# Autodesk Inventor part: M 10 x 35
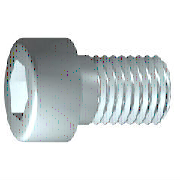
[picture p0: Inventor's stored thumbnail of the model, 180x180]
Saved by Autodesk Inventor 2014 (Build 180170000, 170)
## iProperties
Created: 2009-02
Part Number: M 10 x 35
Material: 강, 연강
Description: 6각머리 태핑 나사
Document SubType Name: Modeling
Standard: KS B 1003
Designer: KYOUNG IL JANG
Standards Organization: KS
Language: ko-KR
Size Designation: M 10 x 35
Categories: <MemberInstance><Categories><Category DisplayName="조임쇠" InternalName="e4da775c-781d-43d5-af7c-5136215cf5a6" Mnemonic="FSTN"><Category DisplayName="볼트" InternalN
Density: 1 g/cm^3
Appearance: 강철
IsCustomPart: 0
Author: KYOUNG IL JANG
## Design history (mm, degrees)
sketch "스케치1"
  geometry: L1 (-2.333, 0)-(35, 0); L2 (35, 0)-(35, 5); L3 (35, 5)-(3.75, 5); L4 (3.75, 5)-(2.83, 5); L5 (2.83, 5)-(0, 5); L6 (0, 5)-(0, 8); L7 (0, 8)-(-10, 8); L8 (-10, 8)-(-10, 4.619); L9 (-10, 4.619)-(-5, 4.619); L10 (-5, 4.619)-(-2.333, 0); L11 (-19, 0)-(44, 0) reference; L12 (0, -1.6)-(0, 9.6) reference; L13 (3.75, 5)-(0, 5)
  constraints: 22 end point, 6 parallel, 2 collinear, 2 perpendicular, 1 horizontal, 1 point on line
  dimensions: "d1" = 31.25 distance from line of L3.end L2 (= GEL); "d2" = 0.92028 distance of L4.end L3.end (computed from GAL); "d3" = 10 distance between parallel lines of L8 L6 (= KOH); "d4" = 5 distance of L8.end L9.end (= INTI); "d5" = 60 deg angle of L10 L1; "d6" = 10 diameter of L3 L1 (= GD); "d7" = 10 diameter of L5 L1 (= BDM); "d8" = 9.2376 diameter of L9 L1 (= 1.1547 x SW); "d9" = 16 diameter of L7 L1 (= KOD); "d26" = 35 distance between parallel lines of L12 L2 (= NLG)
revolve "본체" sketch "스케치1" stored, may be unused: angle "d10" = 90 deg
sketch "스케치2"
  geometry: L1 (0, -11.2)-(0, 11.2) reference; L2 (-11.2, 0)-(11.2, 0) reference; L3 (4.619, 0)-(2.309, -4); L4 (2.309, -4)-(-2.309, -4); L5 (-2.309, -4)-(-4.619, 0); L6 (-4.619, 0)-(-2.309, 4); L7 (-2.309, 4)-(2.309, 4); L8 (2.309, 4)-(4.619, 0); 2 further points
  constraints: 12 end point, 1 coincident, 1 horizontal alignment, 1 point on line, 12 other
extrude "슬롯" join sketch "스케치2" stored distance "d11" = 10; taper "d12" = 0 deg
workplane "Work Plane1"
fillet "Fillet2" dims "d30" = 0.1 (= R)
body "Solid1"
fillet "모깎기1" dims "d17" = 1 (= RR)
feature "스레드" dims "d13" = 31.25 (= GEL), "d14" = 0
chamfer "모따기1" distance "d15" = 0.92018 (= -0.5 x SPD + 0.5 x GD); stored, may be unused: second distance "d16" = 0.92018 (= GUL), angle "d27" = 45 deg
other parameters: "GD" = 10 (= NND) [user parameter; used in 2 equation terms], "NLG" = 35 [user parameter; used in 1 equation term], "GEL" = 31.25 [user parameter; used in 2 equation terms], "KOD" = 16 [user parameter; used in 1 equation term], "KOH" = 10 [user parameter; used in 1 equation term], "INTI" = 5 [user parameter; used in 1 equation term], "GAL" = 0.92018 (= 0.61345 x PTC) [user parameter; used in 1 equation term], "GUL" = 0.92018 (= 0.61345 x PTC) [user parameter; used in 1 equation term], "BDM" = 10 (= NND) [user parameter; used in 1 equation term], "SW" = 8 [user parameter; used in 2 equation terms], "RR" = 1 [user parameter; used in 1 equation term], "SPD" = 8.15965 (= NND - 1.2269 x PTC) [user parameter; used in 1 equation term], "d19" = 0, "d28" = 0, "d29" = 0, "R" = 0.1 [user parameter; used in 1 equation term], "PHH" = 0.4 [user parameter], "GD1" = 8.15965 (= THREADDIA - 1.2269 x PTC) [user parameter], "FAWI" = 45 deg [user parameter], "TPU" = 6.66667 (computed from PTC) [user parameter], "PTC" = 1.5 [user parameter; used in 5 equation terms], "TOA" = 30 deg [user parameter], "E0" = 9.24 (= 1.155 x SW) [user parameter]
